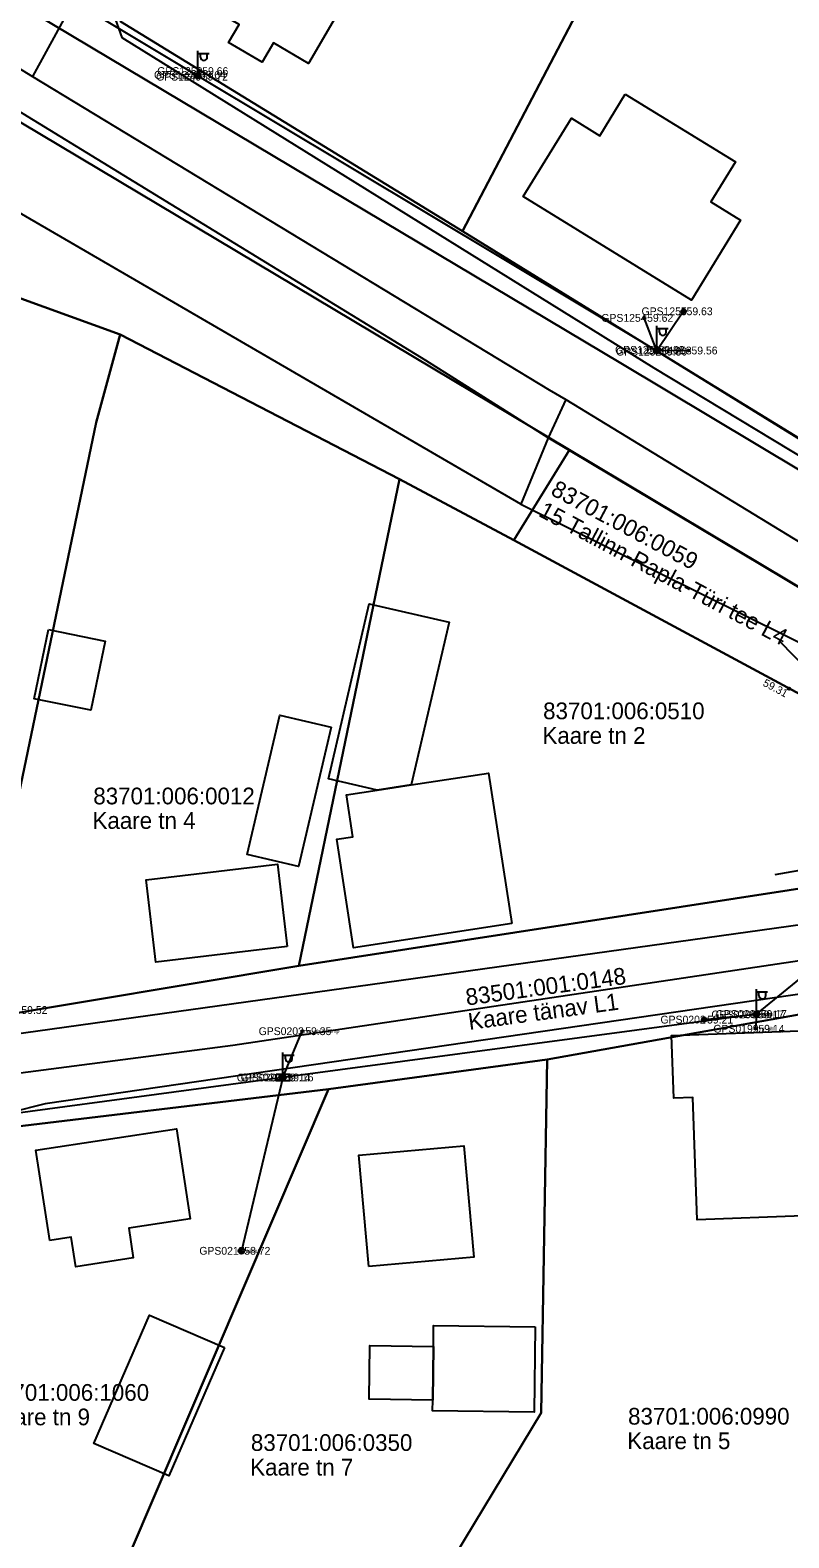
# Model space of a CAD drawing. Extents: x 580119 to 583377, y 6518915 to 6520820.
# Drawn here: x 581712.7 to 581780.8, y 6519692.3 to 6519827.6 of the extents above; entities that cross this region are included whole.
import ezdxf

# ---------------------------------------------------------------- set-up
doc = ezdxf.new("R2010")
doc.units = 0
for name, color, linetype in [('ELRAJATISMP', 7, 'Continuous'), ('Hoone Elu- või ühiskondlik hoone', 7, 'Continuous'), ('Hoone Kõrval- või tootmishoone', 7, 'Continuous'), ('KORGUS-EH2000', 7, 'Continuous'), ('L_AADRESS', 7, 'Continuous'), ('MAAMUDEL', 7, 'Continuous'), ('MOOTKORG-EH2000', 7, 'Continuous'), ('MOOTMPUNKT', 7, 'Continuous'), ('MOOTNR', 7, 'Continuous'), ('MPKAABEL', 7, 'Continuous'), ('MPOHULIIN', 7, 'Continuous'), ('Muu rajatis Katusealune', 7, 'Continuous'), ('PIIR', 7, 'Continuous'), ('POST', 7, 'Continuous'), ('SIOHULIIN', 7, 'Continuous'), ('Tee Kergliiklustee Püsikate', 7, 'Continuous'), ('Tee Liiklusala', 7, 'Continuous'), ('Tee Tugimaantee Püsikate', 7, 'Continuous'), ('Tee Tänav Püsikate', 7, 'Continuous'), ('TUNNUS', 7, 'Continuous')]:
    doc.layers.add(name, color=color, linetype=linetype)

msp = doc.modelspace()

# ---------------------------------------------------------------- linework, layer by layer
at = {"layer": 'ELRAJATISMP'}
for p, q in [((581735.27, 6519733.9), (581735.27, 6519733.31)), ((581735.54, 6519733.9), (581735.54, 6519733.31))]:
    msp.add_line(p, q, dxfattribs=at)
msp.add_lwpolyline([(581734.81, 6519733.9), (581736.01, 6519733.9), (581736.01, 6519733.31), (581734.81, 6519733.31)], close=True, dxfattribs=at)
at = {"layer": 'Hoone Elu- või ühiskondlik hoone'}
for points in [[(581733.78, 6519838.97), (581738.27, 6519836.33), (581737.53, 6519835.06), (581742.2, 6519832.32), (581737.69, 6519824.61), (581734.55, 6519826.45), (581733.54, 6519824.73), (581730.53, 6519826.5), (581731.48, 6519828.12), (581727.2, 6519830.63), (581731.62, 6519838.16), (581732.88, 6519837.43)], [(581766.14, 6519821.85), (581776.03, 6519815.77), (581773.83, 6519812.18), (581776.5, 6519810.54), (581772.08, 6519803.36), (581756.97, 6519812.66), (581761.31, 6519819.7), (581763.85, 6519818.13)], [(581755.95, 6519747.43), (581741.74, 6519745.24), (581740.24, 6519754.98), (581741.69, 6519755.2), (581741.11, 6519758.96), (581743.88, 6519759.39), (581746.93, 6519759.86), (581753.86, 6519760.93)], [(581735.8, 6519745.36), (581724.01, 6519743.95), (581723.13, 6519751.35), (581734.91, 6519752.76)], [(581790.79, 6519738.12), (581791.07, 6519730.65), (581783.42, 6519730.36), (581783.65, 6519724.18), (581781.98, 6519724.11), (581782.09, 6519721.2), (581772.59, 6519720.84), (581772.2, 6519731.81), (581770.5, 6519731.75), (581770.29, 6519737.36)], [(581714.47, 6519718.97), (581713.22, 6519727.07), (581725.84, 6519729.01), (581727.09, 6519720.92), (581721.56, 6519720.07), (581721.97, 6519717.41), (581716.81, 6519716.61), (581716.4, 6519719.27)], [(581743.12, 6519716.64), (581742.21, 6519726.62), (581751.66, 6519727.48), (581752.56, 6519717.49)]]:
    msp.add_lwpolyline(points, close=True, dxfattribs=at)
at = {"layer": 'Hoone Kõrval- või tootmishoone'}
for points in [[(581746.93, 6519759.86), (581743.88, 6519759.39), (581739.49, 6519760.41), (581743.15, 6519776.13), (581750.33, 6519774.46)], [(581714.35, 6519773.81), (581719.45, 6519772.76), (581718.16, 6519766.56), (581713.07, 6519767.6)], [(581739.74, 6519765.05), (581736.8, 6519752.54), (581732.19, 6519753.63), (581735.13, 6519766.13)], [(581730.16, 6519709.36), (581725.16, 6519697.84), (581718.43, 6519700.77), (581723.44, 6519712.28)], [(581758.06, 6519711.23), (581757.96, 6519703.56), (581748.84, 6519703.68), (581748.86, 6519704.65), (581748.92, 6519709.47), (581748.94, 6519711.34)]]:
    msp.add_lwpolyline(points, close=True, dxfattribs=at)
at = {"layer": 'KORGUS-EH2000'}
msp.add_circle((581780.85, 6519768.5), 0.1, dxfattribs=at)
at = {"layer": 'MOOTMPUNKT'}
for centre in [(581727.68, 6519823.59), (581727.87, 6519823.43), (581727.9, 6519823.93), (581767.85, 6519801.78), (581771.39, 6519802.37), (581768.87, 6519798.91), (581771.83, 6519798.85), (581769.1, 6519798.75), (581777.8, 6519739.26), (581778.05, 6519739.3), (581773.23, 6519738.8), (581777.84, 6519737.98), (581737.15, 6519737.76), (581735.26, 6519733.6), (581735.55, 6519733.61), (581731.68, 6519718.05)]:
    msp.add_circle(centre, 0.1, dxfattribs=at)
at = {"layer": 'MPKAABEL'}
for points in [[(581792.57, 6519760.49), (581789.7, 6519762.89), (581788.84, 6519763.52), (581786.52, 6519765.86), (581784.16, 6519768.36), (581782.7, 6519770.02), (581779.98, 6519772.8)], [(581792.88, 6519761.89), (581792.37, 6519762), (581791.76, 6519761.72), (581791.35, 6519760.82), (581791.25, 6519760.05), (581790.9, 6519759.53), (581790.49, 6519759.16), (581790.49, 6519757.88), (581790.66, 6519756.61), (581790.09, 6519754.29), (581789.69, 6519753.9), (581789.06, 6519753.43), (581787.79, 6519753.15), (581786.56, 6519753.02), (581779.58, 6519751.78)]]:
    msp.add_lwpolyline(points, dxfattribs=at)
at = {"layer": 'MPOHULIIN'}
for p, q in [((581727.78, 6519823.51), (581727.9, 6519823.93)), ((581777.92, 6519739.28), (581786.13, 6519745.97)), ((581777.92, 6519739.28), (581777.84, 6519737.98)), ((581735.41, 6519733.61), (581737.15, 6519737.76))]:
    msp.add_line(p, q, dxfattribs=at)
for points in [[(581386.07, 6520026.02), (581416.88, 6520008.2), (581446.3, 6519991.39), (581473.57, 6519975.61), (581504.78, 6519957.66), (581539.72, 6519936.99), (581580.34, 6519912.71), (581617.8, 6519889.38), (581651.14, 6519869.54), (581688.96, 6519846.82), (581727.78, 6519823.51), (581768.99, 6519798.83), (581799.65, 6519780), (581800.76, 6519769.03)], [(581771.83, 6519798.85), (581768.99, 6519798.83), (581767.85, 6519801.78)], [(581735.41, 6519733.61), (581699.78, 6519728.81), (581667.38, 6519727.32), (581632.17, 6519725.65), (581588.51, 6519746.8), (581548.1, 6519772.1), (581506.27, 6519795.87), (581500.22, 6519788.21)], [(581777.92, 6519739.28), (581735.41, 6519733.61), (581731.68, 6519718.05)]]:
    msp.add_lwpolyline(points, dxfattribs=at)
at = {"layer": 'Muu rajatis Katusealune'}
msp.add_lwpolyline([(581748.86, 6519704.65), (581743.16, 6519704.72), (581743.22, 6519709.54), (581748.92, 6519709.47)], close=True, dxfattribs=at)
at = {"layer": 'PIIR'}
for points in [[(581566.91, 6519916.24), (581765.76, 6519797.71), (581790.19, 6519783.08), (581813.81, 6519771.08), (581830.15, 6519765.04), (581850.62, 6519759.88), (581900.47, 6519749.25), (581926.68, 6519743.47), (581927.37, 6519746.39), (581972.8, 6519736.39), (581972.1, 6519733.47), (582022.4, 6519721.85)], [(582437.14, 6519631.09), (582279.12, 6519665.47), (582181.52, 6519686.86), (582133.4, 6519697.08), (582083.05, 6519708.05), (582033.29, 6519719.34), (582022.4, 6519721.85), (581972.1, 6519733.47), (581972.8, 6519736.39), (581927.37, 6519746.39), (581926.68, 6519743.47), (581900.47, 6519749.25), (581850.62, 6519759.88), (581830.15, 6519765.04), (581813.81, 6519771.08), (581790.19, 6519783.08), (581765.76, 6519797.71), (581566.91, 6519916.24)], [(582014.36, 6519714.4), (581954.58, 6519728.06), (581945.07, 6519730.21), (581944.37, 6519727.29), (581898.97, 6519737.29), (581899.66, 6519740.22), (581848.58, 6519751.11), (581827.48, 6519756.43), (581810.2, 6519762.82), (581785.83, 6519775.2), (581761.13, 6519789.94), (581562.34, 6519908.5)], [(581562.34, 6519908.5), (581761.13, 6519789.94), (581756.15, 6519781.82), (581745.87, 6519787.29), (581720.78, 6519800.28), (581709.44, 6519804.4), (581689.84, 6519815.63), (581631.91, 6519849.33)], [(581720.83, 6519828.38), (581751.53, 6519809.56), (581782.73, 6519790.33), (581814.17, 6519771.63), (581824.87, 6519768.18), (581842.25, 6519764.8), (581856.32, 6519767.48), (581864.77, 6519769.48), (581880.15, 6519774.76), (581904.42, 6519766.33), (581939.76, 6519753.92), (581938.22, 6519748.74), (581987.97, 6519734.16), (582025, 6519727.92), (582043.82, 6519724.92), (582041.99, 6519717.52), (582191.36, 6519685.62), (582375.21, 6519645.73)], [(581707.45, 6519738.72), (581736.84, 6519743.64), (581785.72, 6519751.16), (581797.39, 6519753.15), (581818.63, 6519745.83), (581759.12, 6519735.22), (581739.49, 6519732.55), (581707.53, 6519728.73)]]:
    msp.add_lwpolyline(points, dxfattribs=at)
for points in [[(581756.25, 6519899.32), (581788.34, 6519879.84), (581751.53, 6519809.56), (581720.83, 6519828.38)], [(581788.34, 6519879.84), (581797.75, 6519897.83), (581828.31, 6519877.26), (581826.46, 6519873.97), (581802.65, 6519831.88), (581804.59, 6519830.86), (581782.73, 6519790.33), (581751.53, 6519809.56)], [(581707.45, 6519738.72), (581681.12, 6519736.39), (581687.82, 6519766.55), (581689.26, 6519769), (581709.44, 6519804.4), (581720.78, 6519800.28), (581718.64, 6519792.38)], [(581720.78, 6519800.28), (581745.87, 6519787.29), (581736.84, 6519743.64), (581707.45, 6519738.72), (581718.64, 6519792.38)], [(581756.15, 6519781.82), (581761.13, 6519789.94), (581785.83, 6519775.2), (581810.2, 6519762.82), (581827.48, 6519756.43), (581848.58, 6519751.11), (581899.66, 6519740.22), (581898.97, 6519737.29), (581944.37, 6519727.29), (581945.07, 6519730.21), (581954.58, 6519728.06), (581950.45, 6519719.52), (581940.85, 6519717.73), (581876.19, 6519740.16), (581862.95, 6519745.89), (581836.27, 6519746.21), (581821.06, 6519746.26), (581818.91, 6519746.03), (581818.63, 6519745.83), (581797.39, 6519753.15), (581799.19, 6519762.22), (581792.48, 6519765.15), (581788.51, 6519764.43)], [(581745.87, 6519787.29), (581756.15, 6519781.82), (581788.51, 6519764.43), (581785.72, 6519751.16), (581736.84, 6519743.64)], [(581757.43, 6519646.61), (581749.03, 6519634.03), (581724.56, 6519646.71), (581738.8, 6519670.79), (581758.6, 6519703.51), (581759.12, 6519735.22), (581818.63, 6519745.83), (581799.14, 6519713.16), (581792.88, 6519699.16), (581778.97, 6519676.98), (581764.34, 6519656.94)], [(581739.49, 6519732.55), (581759.12, 6519735.22), (581758.6, 6519703.51), (581738.8, 6519670.79), (581716.34, 6519678.43)], [(581688.69, 6519688.3), (581707.53, 6519728.73), (581739.49, 6519732.55), (581716.34, 6519678.43), (581701.05, 6519682.87)]]:
    msp.add_lwpolyline(points, close=True, dxfattribs=at)
at = {"layer": 'POST'}
for p, q in [((581727.78, 6519823.76), (581727.78, 6519825.76)), ((581727.78, 6519825.51), (581728.78, 6519825.51)), ((581728, 6519825.19), (581728, 6519825.51)), ((581728.61, 6519825.19), (581728.61, 6519825.51)), ((581727.78, 6519823.51), (581727.78, 6519823.51)), ((581768.99, 6519799.08), (581768.99, 6519801.08)), ((581768.99, 6519800.83), (581769.99, 6519800.83)), ((581769.21, 6519800.51), (581769.21, 6519800.83)), ((581769.83, 6519800.51), (581769.83, 6519800.83)), ((581768.99, 6519798.83), (581768.99, 6519798.83)), ((581777.92, 6519739.53), (581777.92, 6519741.53)), ((581777.92, 6519741.28), (581778.92, 6519741.28)), ((581778.15, 6519740.96), (581778.15, 6519741.28)), ((581778.76, 6519740.96), (581778.76, 6519741.28)), ((581777.92, 6519739.28), (581777.92, 6519739.28)), ((581735.41, 6519733.86), (581735.41, 6519735.86)), ((581735.41, 6519735.61), (581736.41, 6519735.61)), ((581735.63, 6519735.29), (581735.63, 6519735.61)), ((581736.25, 6519735.29), (581736.25, 6519735.61)), ((581735.41, 6519733.61), (581735.41, 6519733.61))]:
    msp.add_line(p, q, dxfattribs=at)
for points in [[(581771.39, 6519802.37), (581768.99, 6519798.83)], [(581773.23, 6519738.8), (581777.92, 6519739.28)]]:
    msp.add_lwpolyline(points, dxfattribs=at)
for centre, radius in [((581727.78, 6519823.51), 0.25), ((581771.39, 6519802.37), 0.2), ((581768.99, 6519798.83), 0.25), ((581777.92, 6519739.28), 0.25), ((581773.23, 6519738.8), 0.2), ((581735.41, 6519733.61), 0.25), ((581731.68, 6519718.05), 0.25)]:
    msp.add_circle(centre, radius, dxfattribs=at)
for centre in [(581728.31, 6519825.19), (581769.52, 6519800.51), (581778.46, 6519740.96), (581735.94, 6519735.29)]:
    msp.add_arc(centre, 0.306, 180, 0, dxfattribs=at)
at = {"layer": 'SIOHULIIN'}
msp.add_lwpolyline([(581504.78, 6519957.66), (581539.72, 6519936.99), (581580.34, 6519912.71), (581617.8, 6519889.38), (581651.14, 6519869.54), (581688.96, 6519846.82), (581727.78, 6519823.51), (581768.99, 6519798.83), (581799.65, 6519780)], dxfattribs=at)
at = {"layer": 'Tee Kergliiklustee Püsikate'}
for points in [[(581756.77, 6519785.07), (581697.37, 6519819.56), (581695.09, 6519820.88)], [(581756.77, 6519785.07), (581796.7, 6519765.25), (581814.38, 6519755.99)]]:
    msp.add_lwpolyline(points, dxfattribs=at)
at = {"layer": 'Tee Liiklusala'}
for points in [[(581720.38, 6519828.52), (581720.95, 6519826.95), (581768.72, 6519797.3), (581810.21, 6519772.25), (581818.53, 6519768.42), (581826.6, 6519765.66), (581834.64, 6519763.76), (581840.22, 6519763.09), (581848.3, 6519762.14), (581861.54, 6519763.3), (581864.96, 6519764.3), (581868.47, 6519765.32), (581882.93, 6519772.24), (581880.53, 6519775.58), (581877.63, 6519779.57), (581889.27, 6519791.94), (581896.55, 6519800.55), (581903.84, 6519794.86), (581906.33, 6519797.61), (581931.92, 6519825.13), (581939.52, 6519834.18)], [(581705.86, 6519736.75), (581784.65, 6519747.72), (581794.4, 6519749.52), (581803.98, 6519751.42), (581808.27, 6519754.56), (581809.55, 6519756.83), (581808.79, 6519757.42), (581796.03, 6519764.07), (581796.7, 6519765.25), (581797.83, 6519767.23), (581798.2, 6519767.89), (581782.38, 6519777.2), (581759.22, 6519791.01), (581748.24, 6519797.94), (581705.4, 6519824.16)], [(581813.14, 6519581.73), (581814.61, 6519596.33), (581820.11, 6519615.45), (581823.93, 6519625.23), (581847.48, 6519692.07), (581860.77, 6519729.7), (581865.29, 6519740.67), (581864.58, 6519744.64), (581863.32, 6519746.33), (581841.1, 6519747.22), (581827.65, 6519749.65), (581814.59, 6519754.01), (581808.57, 6519747.53), (581803.69, 6519744.78), (581798.27, 6519743.48), (581714.06, 6519731.24), (581710.97, 6519730.47)]]:
    msp.add_lwpolyline(points, dxfattribs=at)
at = {"layer": 'Tee Tugimaantee Püsikate'}
for points in [[(581700.8, 6519830.9), (581712.91, 6519823.44)], [(581712.91, 6519823.44), (581759.32, 6519795.32), (581760.8, 6519794.45)], [(581760.8, 6519794.45), (581789.11, 6519777.2), (581796.84, 6519773.34), (581803.77, 6519768.81), (581812.54, 6519763.96), (581820.98, 6519760.4)]]:
    msp.add_lwpolyline(points, dxfattribs=at)
at = {"layer": 'Tee Tänav Püsikate'}
for points in [[(581775.42, 6519946.31), (581773.32, 6519942.13), (581717.3, 6519831.46), (581712.91, 6519823.44)], [(581760.8, 6519794.45), (581759.22, 6519791.01), (581756.77, 6519785.07)], [(581705.38, 6519733.2), (581730.9, 6519736.52), (581781.79, 6519744.09), (581797.73, 6519746.69), (581808.19, 6519752.25), (581811.44, 6519754.04), (581814.38, 6519755.99)]]:
    msp.add_lwpolyline(points, dxfattribs=at)

# ---------------------------------------------------------------- texts
at = {"layer": 'KORGUS-EH2000'}
msp.add_text(' 59.31', height=0.7, rotation=332.0116, dxfattribs=at).set_placement((581778.21, 6519768.92))
at = {"layer": 'L_AADRESS'}
for s, rotation, p in [('15 Tallinn-Rapla-Türi tee L4', 331.8977, (581758.26, 6519784.04)), ('Kaare tänav L1', 7.7368, (581752.15, 6519737.87))]:
    msp.add_text(s, height=1.5, rotation=rotation, dxfattribs=at).set_placement(p)
for s, p in [('Kaare tn 2', (581758.71, 6519763.55)), ('Kaare tn 4', (581718.31, 6519755.92)), ('Kaare tn 9', (581708.83, 6519702.39)), ('Kaare tn 5', (581766.33, 6519700.25)), ('Kaare tn 7', (581732.47, 6519697.88))]:
    msp.add_text(s, height=1.5, dxfattribs=at).set_placement(p)
at = {"layer": 'MAAMUDEL'}
for s, p in [(' kaabel', (581777.8, 6519739.08)), (' kaabel', (581778.05, 6519739.12)), (' mp_ohl', (581777.84, 6519737.81)), (' mp_ohl7.85mp', (581737.15, 6519737.59)), (' kaabel', (581731.68, 6519717.87))]:
    msp.add_text(s, height=0.35, dxfattribs=at).set_placement(p)
at = {"layer": 'MOOTKORG-EH2000'}
for s, p in [(' 59.64', (581727.68, 6519823.24)), (' 59.72', (581727.87, 6519823.08)), (' 59.66', (581727.9, 6519823.58)), (' 59.62', (581767.85, 6519801.43)), (' 59.63', (581771.39, 6519802.02)), (' 59.82', (581768.87, 6519798.56)), (' 59.80', (581769.1, 6519798.4)), (' 59.56', (581771.83, 6519798.5)), (' 59.52', (581711.66, 6519739.31)), (' 59.17', (581777.8, 6519738.91)), (' 59.17', (581778.05, 6519738.95)), (' 59.35', (581737.15, 6519737.41)), (' 59.21', (581773.23, 6519738.45)), (' 59.14', (581777.84, 6519737.63)), (' 59.14', (581735.26, 6519733.25)), (' 59.16', (581735.55, 6519733.26)), (' 58.72', (581731.68, 6519717.7))]:
    msp.add_text(s, height=0.7, dxfattribs=at).set_placement(p)
at = {"layer": 'MOOTNR'}
for s, p in [('GPS1248 ', (581723.83, 6519823.24)), ('GPS1249 ', (581724.02, 6519823.08)), ('GPS1250 ', (581724.12, 6519823.58)), ('GPS1254 ', (581764, 6519801.43)), ('GPS1255 ', (581767.61, 6519802.02)), ('GPS1251 ', (581765.23, 6519798.56)), ('GPS1252 ', (581765.32, 6519798.4)), ('GPS1253 ', (581768.05, 6519798.5)), ('GPS0200 ', (581773.88, 6519738.91)), ('GPS0201 ', (581774.27, 6519738.95)), ('GPS0203 ', (581733.23, 6519737.41)), ('GPS0202 ', (581769.31, 6519738.45)), ('GPS0199 ', (581774.06, 6519737.63)), ('GPS0204 ', (581731.27, 6519733.25)), ('GPS0205 ', (581731.63, 6519733.26)), ('GPS0217 ', (581727.9, 6519717.7))]:
    msp.add_text(s, height=0.7, dxfattribs=at).set_placement(p)
at = {"layer": 'TUNNUS'}
for s, rotation, p in [('83701:006:0059', 331.8977, (581759.36, 6519785.95)), ('83501:001:0148', 7.7368, (581751.92, 6519740.06))]:
    msp.add_text(s, height=1.5, rotation=rotation, dxfattribs=at).set_placement(p)
for s, p in [('83701:006:0510', (581758.77, 6519765.76)), ('83701:006:0012', (581718.38, 6519758.12)), ('83701:006:1060', (581708.89, 6519704.59)), ('83701:006:0990', (581766.4, 6519702.45)), ('83701:006:0350', (581732.53, 6519700.09))]:
    msp.add_text(s, height=1.5, dxfattribs=at).set_placement(p)

doc.saveas('drawing.dxf')
